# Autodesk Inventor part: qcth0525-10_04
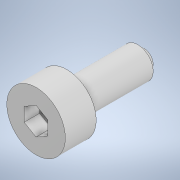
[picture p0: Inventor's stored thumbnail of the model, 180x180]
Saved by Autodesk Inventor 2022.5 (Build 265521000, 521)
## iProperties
Created: 2022-02
Part Number: qcth0525-10_04
Material: 一般
Document SubType Name: Modeling
Designer: ImaoCorp
Density: 1 g/cm^3
Appearance: 既定
Author: ImaoCorp
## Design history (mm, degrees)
feature "qcth0525-10_04"
node "ソリッド1"
